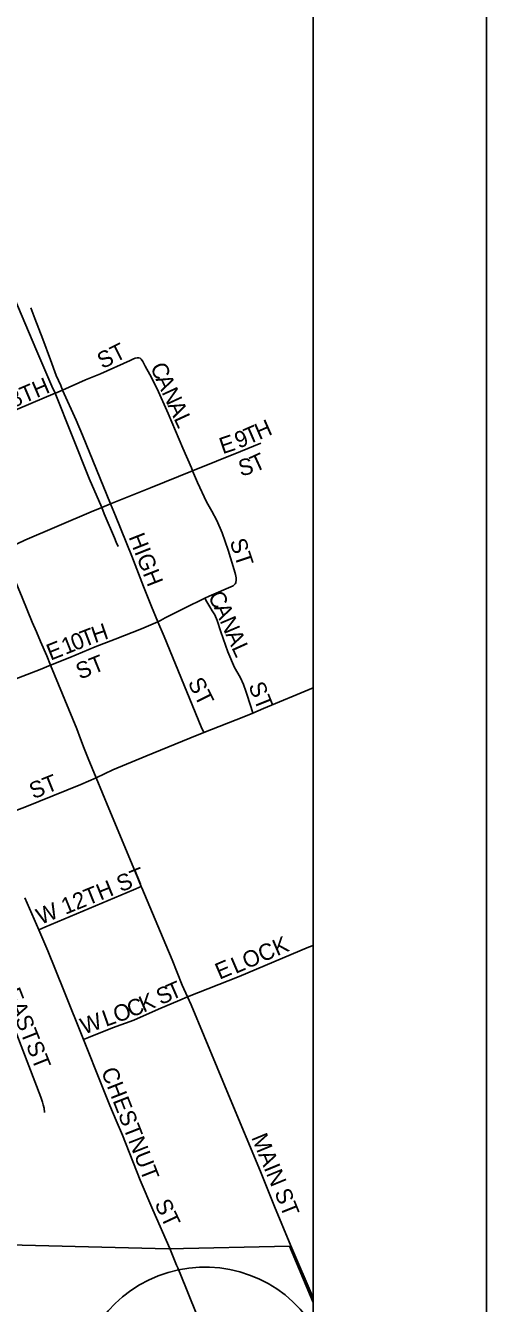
# Model space of a CAD drawing. Extents: x 0 to 34, y 0 to 22.
# Drawn here: x 30.651 to 30.917, y 14.628 to 15.366 of the extents above; entities that cross this region are included whole.
import ezdxf

# ---------------------------------------------------------------- set-up
doc = ezdxf.new("R2010")
doc.units = 0
for name, color, linetype in [('GM_X_Adjacent_County', 7, 'Continuous'), ('GM_X_City_Street', 7, 'Continuous'), ('GM_X_City_Street_Text', 7, 'Continuous'), ('GM_X_Corporation', 7, 'Continuous'), ('GM_X_County', 7, 'Continuous'), ('GM_X_State_Route', 7, 'Continuous'), ('GM_X_Township', 7, 'Continuous'), ('GM_X_Township_Road', 7, 'Continuous'), ('GM_X_Township_Subdivision', 7, 'Continuous'), ('GM_X_Unincorporated', 7, 'Continuous'), ('SH_Data', 7, 'Continuous')]:
    doc.layers.add(name, color=color, linetype=linetype)

msp = doc.modelspace()

# ---------------------------------------------------------------- linework, layer by layer
at = {"layer": 'GM_X_Adjacent_County'}
msp.add_lwpolyline([(24.01667, 18.0693), (24.01667, 14.1), (30.81667, 14.1), (30.81667, 17.81737)], dxfattribs=at)
at = {"layer": 'GM_X_City_Street'}
for points in [[(30.66776, 15.15339), (30.66601, 15.15747), (30.65677, 15.17901), (30.64034, 15.21782)], [(30.67211, 15.15529), (30.67103, 15.1578), (30.66851, 15.16367), (30.66517, 15.17268), (30.66074, 15.18471), (30.65603, 15.19662), (30.65388, 15.20264)], [(30.67211, 15.15529), (30.6854, 15.16107), (30.69407, 15.16464), (30.71104, 15.17233), (30.71274, 15.17312), (30.71402, 15.17364), (30.71517, 15.17392), (30.71616, 15.17388)], [(30.74713, 15.10865), (30.74642, 15.11041), (30.74155, 15.12179), (30.733, 15.14175), (30.72665, 15.15588), (30.72256, 15.16423), (30.71983, 15.16904), (30.71838, 15.17178), (30.71739, 15.17312), (30.71691, 15.17364), (30.71616, 15.17388)], [(30.61032, 15.12891), (30.61341, 15.13028), (30.61911, 15.1328), (30.66776, 15.15339)], [(30.66776, 15.15339), (30.66813, 15.15355), (30.67211, 15.15529)], [(30.69477, 15.08749), (30.68742, 15.10423), (30.66776, 15.15339)], [(30.69973, 15.08951), (30.68359, 15.12914), (30.67996, 15.13779), (30.67211, 15.15529)], [(30.74713, 15.10865), (30.77484, 15.11984), (30.78645, 15.12459)], [(30.69973, 15.08951), (30.7228, 15.09883), (30.74713, 15.10865)], [(30.77215, 15.04405), (30.77233, 15.04564), (30.77229, 15.04686), (30.77212, 15.04786), (30.77194, 15.0487), (30.77118, 15.05147), (30.7677, 15.06284), (30.76416, 15.07282), (30.76109, 15.07988), (30.75817, 15.08533), (30.75523, 15.09076), (30.7499, 15.10185), (30.74713, 15.10865)], [(30.63742, 15.06251), (30.65037, 15.0686), (30.68858, 15.08499), (30.69477, 15.08749)], [(30.69477, 15.08749), (30.69973, 15.08951)], [(30.70418, 15.06504), (30.70314, 15.06749), (30.702, 15.07002), (30.69622, 15.08381), (30.69477, 15.08749)], [(30.72709, 15.02151), (30.7234, 15.03027), (30.71888, 15.04195), (30.71201, 15.05941), (30.70269, 15.08263), (30.69973, 15.08951)], [(30.75422, 15.03503), (30.75662, 15.03619), (30.77053, 15.0423), (30.77118, 15.04283), (30.77174, 15.04339), (30.77215, 15.04405)], [(30.72709, 15.02151), (30.72857, 15.02214), (30.73129, 15.02368), (30.74248, 15.02937), (30.75422, 15.03503)], [(30.78195, 14.96877), (30.78093, 14.97191), (30.77785, 14.98139), (30.77644, 14.98528), (30.77483, 14.98904), (30.77331, 14.99176), (30.77133, 14.99515), (30.76756, 15.00421), (30.76343, 15.01561), (30.76125, 15.02225), (30.76002, 15.02548), (30.7585, 15.0279), (30.75715, 15.03015), (30.75536, 15.03291), (30.75422, 15.03503)], [(30.66524, 14.9964), (30.67641, 15.00089), (30.69085, 15.00704), (30.70256, 15.01153), (30.7177, 15.01743), (30.72709, 15.02151)], [(30.75357, 14.95752), (30.75218, 14.96086), (30.74374, 14.98109), (30.73069, 15.01295), (30.72709, 15.02151)], [(30.60437, 14.97069), (30.64173, 14.98723), (30.65912, 14.99401), (30.66524, 14.9964)], [(30.6311, 14.90735), (30.636, 14.9089), (30.64168, 14.91111), (30.65028, 14.9144), (30.68274, 14.92753), (30.69145, 14.93139)], [(30.71754, 14.86863), (30.71473, 14.87542), (30.69888, 14.91377), (30.69145, 14.93139)], [(30.65834, 14.84366), (30.66189, 14.84515), (30.7131, 14.86675), (30.71754, 14.86863)], [(30.74427, 14.80494), (30.74118, 14.81179), (30.73542, 14.82624), (30.73161, 14.83503), (30.71788, 14.86782), (30.71754, 14.86863)], [(30.65834, 14.84366), (30.65042, 14.86209)], [(30.66168, 14.73817), (30.66142, 14.74073), (30.661, 14.74272), (30.66062, 14.74412), (30.6596, 14.74701), (30.63424, 14.81277), (30.62739, 14.82973), (30.62144, 14.84381), (30.61857, 14.8506)], [(30.68421, 14.78032), (30.67295, 14.80855), (30.66353, 14.83157), (30.65834, 14.84366)], [(30.74427, 14.80494), (30.77399, 14.8167), (30.81407, 14.83358), (30.81667, 14.83469)], [(30.68421, 14.78032), (30.68706, 14.78148), (30.70084, 14.78705), (30.71315, 14.79147), (30.72756, 14.79789), (30.73976, 14.80304), (30.74427, 14.80494)], [(30.80379, 14.6613), (30.79432, 14.68399), (30.78624, 14.70417), (30.76885, 14.74608), (30.74632, 14.80039), (30.74427, 14.80494)], [(30.73794, 14.65012), (30.73395, 14.65976), (30.72426, 14.682), (30.71687, 14.69908), (30.70661, 14.72506), (30.70301, 14.73367), (30.69932, 14.74215), (30.69481, 14.75371), (30.68421, 14.78032)]]:
    msp.add_lwpolyline(points, dxfattribs=at)
at = {"layer": 'GM_X_Corporation'}
msp.add_line((30.81667, 14.62861), (30.81667, 15.6406), dxfattribs=at)
msp.add_lwpolyline([(29.75791, 15.20851), (29.79058, 15.21093), (29.86115, 15.29432), (29.91553, 15.1943), (29.9416, 15.13863), (29.94194, 15.10088), (29.94871, 15.04567), (29.96989, 14.94591), (30.07764, 14.93075), (30.06917, 14.68585), (30.09828, 14.68409), (30.30666, 14.67751), (30.32534, 14.67859), (30.34695, 14.67725), (30.50269, 14.66532), (30.73315, 14.65946), (30.803, 14.661), (30.81667, 14.62861)], dxfattribs=at)
at = {"layer": 'GM_X_County'}
msp.add_lwpolyline([(24.01667, 18.0693), (24.01667, 14.1), (30.81667, 14.1), (30.81667, 17.81737)], dxfattribs=at)
at = {"layer": 'GM_X_State_Route'}
for points in [[(30.63742, 15.06251), (30.64285, 15.04994), (30.6488, 15.03548), (30.65465, 15.02134), (30.65703, 15.01572), (30.65943, 15.01015), (30.66299, 15.00186), (30.66524, 14.9964), (30.68036, 14.95966), (30.68245, 14.95396), (30.68463, 14.94828), (30.68697, 14.94263), (30.69145, 14.93139)], [(30.69145, 14.93139), (30.70104, 14.93595), (30.72021, 14.9439), (30.74555, 14.95438), (30.75357, 14.95752), (30.77675, 14.96653), (30.78195, 14.96877), (30.78814, 14.97144), (30.81667, 14.98339)]]:
    msp.add_lwpolyline(points, dxfattribs=at)
at = {"layer": 'GM_X_Township'}
msp.add_lwpolyline([(30.08466, 14.1), (30.81667, 14.1), (30.81667, 15.62899)], dxfattribs=at)
at = {"layer": 'GM_X_Township_Road'}
msp.add_lwpolyline([(30.81667, 14.63125), (30.80379, 14.6613)], dxfattribs=at)
at = {"layer": 'GM_X_Township_Subdivision'}
msp.add_lwpolyline([(30.76383, 14.58515), (30.76339, 14.58626), (30.75783, 14.60081), (30.74326, 14.63726), (30.73864, 14.64844), (30.73794, 14.65012)], dxfattribs=at)
at = {"layer": 'GM_X_Unincorporated'}
msp.add_arc((30.75428, 14.57454), 0.0744, 33.02444, 326.97556, dxfattribs=at)
at = {"layer": 'SH_Data'}
for points in [[(23.91667, 21), (30.91667, 21), (30.91667, 14), (23.91667, 14)], [(24.01667, 20.9), (30.81667, 20.9), (30.81667, 14.1), (24.01667, 14.1)]]:
    msp.add_lwpolyline(points, close=True, dxfattribs=at)

# ---------------------------------------------------------------- texts
at = {"layer": 'GM_X_City_Street_Text'}
for s, rotation, p in [('ST', 26.56505, (30.69509, 15.16724)), ('C', 293.24005, (30.72256, 15.16875)), ('8TH', 22.99194, (30.64351, 15.14478)), ('A', 294.59618, (30.72562, 15.16164)), ('N', 294.79755, (30.72911, 15.15403)), ('A', 294.76598, (30.7326, 15.14646)), ('L', 294.77954, (30.73609, 15.13889)), ('H', 23.50077, (30.78551, 15.12631)), ('9', 21.95582, (30.77372, 15.12137)), ('T', 23.42071, (30.77938, 15.12365)), ('E', 18.60778, (30.76449, 15.11817)), ('S', 13.65193, (30.77481, 15.10538)), ('T', 24.63734, (30.78315, 15.1076)), ('HIGH', 291.50388, (30.71004, 15.07047)), ('ST', 288.42622, (30.76841, 15.06788)), ('C', 300.63055, (30.75563, 15.03592)), ('A', 293.7295, (30.75931, 15.02973)), ('H', 18.93941, (30.69067, 15.00905)), ('N', 292.99482, (30.76265, 15.02213)), ('1', 21.75406, (30.67373, 15.00237)), ('0', 21.76382, (30.67915, 15.00453)), ('T', 21.04536, (30.68454, 15.00668)), ('A', 294.29414, (30.766, 15.01425)), ('E', 21.77097, (30.66522, 14.99897)), ('L', 294.46305, (30.76944, 15.00662)), ('ST', 21.79136, (30.6821, 14.98801)), ('ST', 296.56506, (30.74414, 14.98645)), ('ST', 291.78635, (30.7792, 14.98464)), ('ST', 21.80392, (30.65522, 14.91897)), ('W 12TH ST', 22.10633, (30.65938, 14.84647)), ('LOCK', 23.19783, (30.77185, 14.81812)), ('E', 23.21366, (30.76268, 14.81478)), ('T', 23.5574, (30.73481, 14.80277)), ('EAST', 291.50162, (30.63837, 14.80797)), ('K', 23.51344, (30.71876, 14.79578)), ('S', 23.54461, (30.7287, 14.8001)), ('O', 19.78141, (30.70336, 14.78985)), ('C', 22.41106, (30.71165, 14.79284)), ('W', 19.47174, (30.68446, 14.78316)), ('L', 19.47186, (30.69703, 14.78761)), ('ST', 291.80393, (30.65087, 14.77715)), ('CHESTNUT', 291.37266, (30.69421, 14.76214)), ('MAIN', 292.37982, (30.78086, 14.72383)), ('ST', 295.0177, (30.725, 14.68557)), ('ST', 291.80393, (30.7942, 14.69214))]:
    msp.add_text(s, height=0.00947, rotation=rotation, dxfattribs=at).set_placement(p)

doc.saveas('drawing.dxf')
